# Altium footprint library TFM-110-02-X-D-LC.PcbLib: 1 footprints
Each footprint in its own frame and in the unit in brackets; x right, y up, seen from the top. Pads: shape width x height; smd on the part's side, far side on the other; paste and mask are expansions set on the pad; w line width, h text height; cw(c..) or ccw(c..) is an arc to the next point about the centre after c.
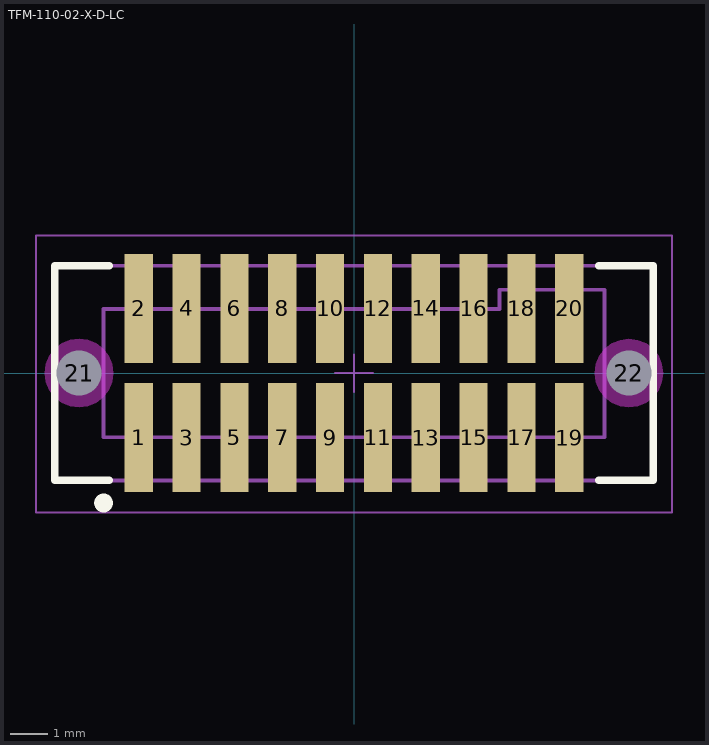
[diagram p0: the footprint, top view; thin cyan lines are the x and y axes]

## TFM-110-02-X-D-LC [mm] "1.27mm pitch, 20 pin, terminal strip; w/locking clips, SMT"
height 5.72
pads (22):
  rect 0.75x2.9 smd mask+0: 1(-5.715,-1.714) 2(-5.715,1.714) 3(-4.445,-1.714) 4(-4.445,1.714) 5(-3.175,-1.714) 6(-3.175,1.714) 7(-1.905,-1.714) 8(-1.905,1.714) 9(-0.635,-1.714) 10(-0.635,1.714) 11(0.635,-1.714) 12(0.635,1.714) 13(1.905,-1.714) 14(1.905,1.714) 15(3.175,-1.714) 16(3.175,1.714) 17(4.445,-1.714) 18(4.445,1.714) 19(5.715,-1.714) 20(5.715,1.714)
  round 1 hole 1.2 unplated mask+0: 21(-7.302,0) 22(7.302,0)
Top Overlay:
  circle w0.25: c-6.65,-3.45 r0.125
  lines w0.2: -6.5,-2.85 -7.95,-2.85 -7.95,2.85 -6.5,2.85 ; 6.5,-2.85 7.95,-2.85 7.95,2.85 6.5,2.85
Keep-Out Layer:
  pour cut-out: 8.21,0 8.18,0.235 8.089,0.454 7.945,0.642 7.757,0.786 7.538,0.877 7.303,0.908 7.068,0.877 6.849,0.786 6.661,0.642 6.517,0.454 6.426,0.235 6.395,0 6.426,-0.235 6.517,-0.454 6.661,-0.642 6.849,-0.786 7.068,-0.877 7.303,-0.908 7.538,-0.877 7.757,-0.786 7.945,-0.642 8.089,-0.454 8.18,-0.235
  pour cut-out: -6.393,0 -6.424,0.235 -6.515,0.455 -6.66,0.643 -6.848,0.787 -7.067,0.878 -7.303,0.909 -7.538,0.878 -7.757,0.787 -7.946,0.643 -8.09,0.455 -8.181,0.235 -8.212,0 -8.181,-0.235 -8.09,-0.455 -7.946,-0.643 -7.757,-0.787 -7.538,-0.878 -7.303,-0.909 -7.067,-0.878 -6.848,-0.787 -6.66,-0.643 -6.515,-0.455 -6.424,-0.235
Mechanical 12:
  lines w0.001: -7.95,-2.85 -7.95,2.85 7.95,2.85 7.95,-2.85 -7.95,-2.85
Mechanical 13:
  lines w0.1: -7.95,-2.85 -7.95,2.85 7.95,2.85 7.95,-2.85 -7.95,-2.85 ; -6.655,-1.702 -6.655,1.702 3.861,1.702 3.861,2.21 6.655,2.21 6.655,-1.702 -6.655,-1.702
  text ".Designator" at 0,-0.127 h1.52
Mechanical 15:
  lines w0.05: -0.5,0 0.5,0 ; 0,-0.5 0,0.5 ; -8.45,-3.7 -8.45,3.65 8.45,3.65 8.45,-3.7 -8.45,-3.7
